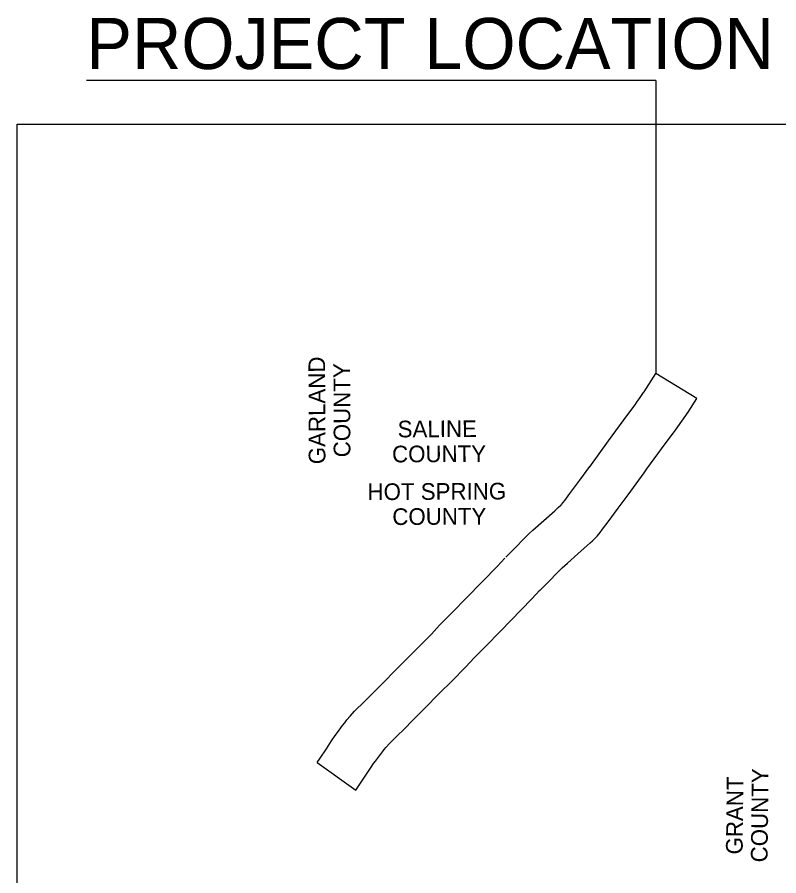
# Model space of a CAD drawing. Extents: x -984 to 3998, y 83 to 2143.
# Drawn here: x 215 to 751, y 1535 to 2140 of the extents above; entities that cross this region are included whole.
import ezdxf

# ---------------------------------------------------------------- set-up
doc = ezdxf.new("R2010")
doc.units = 0
for name, color, linetype in [('Level 13', 7, 'Continuous'), ('Level 2', 7, 'Continuous'), ('Level 46', 7, 'Continuous'), ('Level 57', 7, 'Continuous')]:
    doc.layers.add(name, color=color, linetype=linetype)

msp = doc.modelspace()

# ---------------------------------------------------------------- linework, layer by layer
at = {"layer": 'Level 2'}
for p, q in [((693.48, 1871.01), (664.83, 1888.48)), ((618.17, 1822.91), (631.43, 1841.14)), ((645.26, 1803.21), (656.44, 1818.58)), ((582.78, 1735.5), (585.51, 1738.31)), ((426.15, 1614.64), (453.52, 1595.17))]:
    msp.add_line(p, q, dxfattribs=at)
for points in [[(656.42, 1875.56), (664.83, 1888.48)], [(631.43, 1841.14), (644.32, 1858.68), (650.06, 1866.58), (651.45, 1868.47), (653.78, 1871.7), (656.08, 1875.08), (656.42, 1875.56)], [(687.57, 1861.31), (693.48, 1871.01)], [(656.44, 1818.58), (658.47, 1821.37), (671.37, 1838.92), (677.1, 1846.8), (678.54, 1848.75), (687.57, 1861.31)], [(578.09, 1778.12), (593.59, 1791.92), (595.98, 1794.24), (597.93, 1795.89), (597.99, 1795.94), (598.37, 1796.34), (599.43, 1797.61), (600.59, 1799.12), (604.26, 1803.99), (611.27, 1813.55), (618.23, 1822.99)], [(602.42, 1754.99), (609.78, 1761.48), (616.4, 1767.37), (618.49, 1769.4), (620.12, 1770.77), (621.53, 1772.08), (623.4, 1774.05), (625.59, 1776.68), (627.26, 1778.86), (631.14, 1783.99), (638.26, 1793.7), (645.2, 1803.12)], [(559.17, 1759.23), (562.13, 1762.28), (575.55, 1775.78), (578.09, 1778.12)], [(531.42, 1730.53), (553.18, 1752.8), (558.46, 1758.53)], [(585.65, 1738.41), (586.03, 1738.81), (598.78, 1751.63), (602.42, 1754.99)], [(465.15, 1663.16), (488.92, 1687.17), (497.01, 1695.33), (506.69, 1705.02), (512.38, 1711.25), (517.49, 1716.58), (521.26, 1720.17), (531.45, 1730.56)], [(555.39, 1707.12), (577.49, 1729.75), (583.1, 1735.84)], [(491.52, 1642.17), (501.36, 1652.12), (512.71, 1663.59), (520.75, 1671.69), (530.92, 1681.87), (536.84, 1688.36), (541.15, 1692.85), (544.78, 1696.31), (555.36, 1707.09)], [(432.73, 1624.18), (436.38, 1629.74), (438.92, 1633.51), (440.67, 1635.74), (444.17, 1640.54), (445.65, 1642.4), (447.24, 1644.53), (449.39, 1647.09), (452.61, 1650.64), (454.94, 1653.18), (457.17, 1655.27), (465.15, 1663.16)], [(460.6, 1605.58), (464.27, 1611.19), (466.02, 1613.78), (467.39, 1615.53), (470.83, 1620.23), (472.2, 1621.96), (473.51, 1623.71), (474.63, 1625.05), (477.38, 1628.09), (478.79, 1629.62), (480.4, 1631.13), (489.58, 1640.21), (491.52, 1642.17)], [(426.15, 1614.64), (428.32, 1617.68), (432.73, 1624.18)], [(453.52, 1595.17), (460.6, 1605.58)]]:
    msp.add_lwpolyline(points, dxfattribs=at)
at = {"layer": 'Level 46'}
for q in [(263.71, 2095.04), (664.83, 1888.48)]:
    msp.add_line((664.83, 2095.04), q, dxfattribs=at)
at = {"layer": 'Level 57'}
msp.add_lwpolyline([(215, 2064.18), (946.14, 2064.18), (946.14, 1419.54), (215, 1419.54)], close=True, dxfattribs=at)

# ---------------------------------------------------------------- texts
at = {"layer": 'Level 13'}
for s, rotation, p in [('GARLAND', 90.15841, (432.04, 1824.67)), ('COUNTY', 90.15841, (449.63, 1829.57)), ('SALINE', 0.30251, (482.93, 1843.57)), ('COUNTY', 0.30251, (479, 1825.95)), ('HOT SPRING', 0.30251, (461.72, 1799.37)), ('COUNTY', 0.30251, (479.18, 1781.86)), ('COUNTY', 89.3513, (743.34, 1544.16)), ('GRANT', 89.3513, (725.8, 1549.74))]:
    msp.add_text(s, height=11.733, rotation=rotation, dxfattribs=at).set_placement(p)
at = {"layer": 'Level 2'}
msp.add_text('PROJECT LOCATION', height=36, dxfattribs=at).set_placement((263.71, 2103.04))

doc.saveas('drawing.dxf')
